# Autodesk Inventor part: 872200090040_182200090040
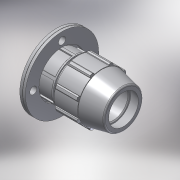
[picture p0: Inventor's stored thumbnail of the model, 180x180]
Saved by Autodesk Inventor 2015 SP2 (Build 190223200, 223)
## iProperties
Created: 2017-02
Part Number: 872200090040_182200090040
Material: PVC-Piping
Description: PLASSON COMPRESSION FLANGE ADAPTOR 90-4"
Document SubType Name: Modeling
Designer: KIM
Mass: 92.6774 g
Surface Area: 199.44 cm^2
Volume: 66.1981 cm^3
Density: 1.4 g/cm^3
Appearance: Smooth - White
Author: KIM
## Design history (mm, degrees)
derived "87220.ipt"
feature "Solid1::87220.ipt"
tag "TaggingFeature1"
body "Solid1"
other parameters: "d4" = 27.71429, "d5" = 62.08, "d7" = 152, "d9" = 27.71429, "d11" = 5.54286, "d12" = 121.6, "d13" = 120 deg, "d14" = 117, "d15" = 12 deg, "d18" = 4.5, "d19" = 35 deg, "d20" = 17.5 deg, "d21" = 141.36, "d23" = 0, "d25" = 360 deg, "d27" = 3.04, "d34" = 7.6, "d36" = 0, "d42" = 67.9, "d43" = 4.56, "d46" = 2.7, "d53" = 1.8, "d55" = 360 deg, "d70" = 194, "d73" = 16.16667, "d74" = 90 deg, "d75" = 0.3, "d77" = 18, "d80" = 0, "d82" = 360 deg, "d85" = 129.2, "d86" = 121.6, "d87" = 2.75, "d88" = 0.3, "d93" = 9.7, "d94" = 182, "d95" = 81, "E_" = 152, "H_" = 194, "l_" = 182, "S_" = 18
